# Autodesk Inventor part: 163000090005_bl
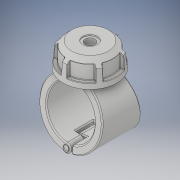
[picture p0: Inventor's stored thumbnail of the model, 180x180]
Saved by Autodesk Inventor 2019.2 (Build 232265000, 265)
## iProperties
Created: 2022-02
Part Number: 163000090005_bl
Material: Generic
Description: Plassadle Threaded 90x1/2''
Document SubType Name: Modeling
Designer: comp2
Density: 1 g/cm^3
Appearance: Default
Author: comp2
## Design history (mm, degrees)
derived "16300.ipt"
feature "Solid1::16300.ipt" dims "ScaleForDerivedMember" = 10
feature "Solid2::16300.ipt" dims "ScaleForDerivedMember" = 10
feature "Solid3::16300.ipt" dims "ScaleForDerivedMember" = 10
feature "Solid4::16300.ipt" dims "ScaleForDerivedMember" = 10
tag "TaggingFeature1"
body "Solid1"
body "Solid2"
body "Solid3"
body "Solid4"
other parameters: "d2" = 119 [user parameter], "d3" = 45 [user parameter], "d7" = 113.05 [user parameter], "d8" = 85 deg [user parameter], "d9" = 45 deg [user parameter], "d10" = 102 [user parameter], "d11" = 49 [user parameter], "d12" = 31.2165 [user parameter], "d13" = 42.84 [user parameter], "d14" = 27.9465 [user parameter], "d42" = 2.9 [user parameter], "d49" = 2.38 [user parameter], "d50" = 94 [user parameter], "d51" = 0 [user parameter], "d52" = 20.3 [user parameter], "d53" = 65.45 [user parameter], "d54" = 32.9 [user parameter], "d55" = 0 [user parameter], "d56" = 18.8 [user parameter], "d57" = 18.8 [user parameter], "d59" = 0 [user parameter], "d60" = 94 [user parameter], "d61" = 0 [user parameter], "d62" = 32.9 [user parameter], "d63" = 0 [user parameter], "d65" = 0 [user parameter], "d67" = 0 [user parameter], "d69" = 0 [user parameter], "d70" = 1 [user parameter], "d71" = 90.24 [user parameter], "d72" = 0 [user parameter], "d73" = 2 [user parameter], "d78" = 86.7 [user parameter], "d79" = 5.1 [user parameter], "d80" = 60 deg [user parameter], "d81" = 5.1 [user parameter], "d84" = 0 [user parameter], "d85" = 1 [user parameter], "d87" = 360 deg [user parameter], "d122" = 49 [user parameter], "d124" = 42.80128 [user parameter], "d125" = 2.22975 [user parameter], "d127" = 163 [user parameter], "d129" = 18.631 [user parameter], "d130" = 15.83635 [user parameter], "d131" = 31.85 [user parameter], "d132" = 45 deg [user parameter], "d133" = 22.295 [user parameter], "d134" = 9.3155 [user parameter], "d136" = 0 [user parameter], "d138" = 0 [user parameter], "d1" = 25 [user parameter], "B" = 119 [user parameter], "L" = 94 [user parameter], "E_" = 54 [user parameter], "E1" = 102 [user parameter], "H1" = 163 [user parameter], "H2" = 49 [user parameter], "H3" = 78 [user parameter], "H_costum" = 49 [user parameter], "Rp" = 18.631 [user parameter], "d128" = 44.595 [user parameter]
